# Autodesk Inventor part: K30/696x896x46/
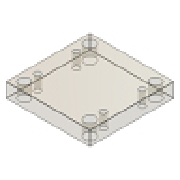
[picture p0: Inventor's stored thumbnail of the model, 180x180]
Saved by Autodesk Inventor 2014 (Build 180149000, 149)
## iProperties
IsCustomPart: 1
Created: 2009-11
Part Number: K30/696x896x46/
Material: DIN 1.1730
Description: Support Plate
Document SubType Name: Modeling
Designer: gaom
Standard Revision: 1
Manufacturer: HASCO
Language: en-US
Size Designation: 696x896x46/
Categories: <MemberInstance><Categories><Category DisplayName="Mold" InternalName="349578f2-f4d4-4954-8c09-8e99297a61c0" Mnemonic="MOLD"><Category DisplayName="Mold Plates"
Density: 7.82 g/cm^3
Appearance: Polycarbonate - Smoked
Author: gaom
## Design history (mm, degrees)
sketch "Sketch1"
  geometry: L1 (-348, 448)-(348, 448); L2 (348, 448)-(348, -448); L3 (348, -448)-(-348, -448); L4 (-348, -448)-(-348, 448); 5 further points
  constraints: 8 end point, 2 midpoint, 2 parallel, 1 horizontal, 1 horizontal alignment, 1 perpendicular, 1 vertical alignment
  dimensions: "d126" = 696 distance between parallel lines of L2 L4 (= W_); "d127" = 896 distance between parallel lines of L3 L1 (= L); "d130" = 296 horizontal distance of point (0, 0) point (-296, 337) (= 0.5 x S1_W); "d131" = 337 vertical distance of point (0, 0) point (-296, 337) (= 0.5 x S1_L); "d132" = 396 vertical distance of point (0, 0) point (-296, 396) (= 0.5 x LS_L); "d133" = 296 horizontal distance of point (0, 0) point (-296, 396) (= 0.5 x LS_W)
extrude "Extrusion1" new body sketch "Sketch1" distance "d20" = 46 (= H_); taper "d30" = 0 deg
sketch "Sketch2"
  geometry: 4 further points
hole "Hole12" sketch "Sketch2" at (-142, -279.032), (78, -279.032), (-78, 279.032), (142, 279.032) diameter "d176" = 3.4; stored, may be unused: countersink angle "d180" = 90 deg, drill point angle "d182" = 0 deg; dims "d177" = 6, "d178" = 4, "d179" = 2, "d181" = 8
sketch "Sketch3"
  geometry: 4 further points
hole "Hole13" sketch "Sketch3" at (-154, -180.032), (66, -180.032), (-66, 180.032), (154, 180.032) diameter "d183" = 3.4; stored, may be unused: countersink angle "d187" = 90 deg, drill point angle "d189" = 0 deg; dims "d184" = 6, "d185" = 4, "d186" = 2, "d188" = 8
sketch "Sketch4"
  geometry: 4 further points
hole "Hole14" sketch "Sketch4" at (-78, -279.032), (142, -279.032), (-142, 279.032), (78, 279.032) diameter "d190" = 3.4; stored, may be unused: countersink angle "d194" = 90 deg, drill point angle "d196" = 0 deg; dims "d191" = 6, "d192" = 4, "d193" = 2, "d195" = 8
sketch "Sketch5"
  geometry: 4 further points
hole "Hole15" sketch "Sketch5" at (-66, -180.032), (154, -180.032), (-154, 180.032), (66, 180.032) diameter "d197" = 3.4; stored, may be unused: countersink angle "d201" = 90 deg, drill point angle "d203" = 0 deg; dims "d198" = 6, "d199" = 4, "d200" = 2, "d202" = 8
sketch "Sketch6"
  geometry: 4 further points
hole "Hole16" sketch "Sketch6" at (-154, -65.032), (66, -65.032), (-66, 65.032), (154, 65.032) diameter "d204" = 3.4; stored, may be unused: countersink angle "d208" = 90 deg, drill point angle "d210" = 0 deg; dims "d205" = 6, "d206" = 4, "d207" = 2, "d209" = 8
sketch "Sketch7"
  geometry: 4 further points
hole "Hole17" sketch "Sketch7" at (-66, -65.032), (154, -65.032), (-154, 65.032), (66, 65.032) diameter "d211" = 3.4; stored, may be unused: countersink angle "d215" = 90 deg, drill point angle "d217" = 0 deg; dims "d212" = 6, "d213" = 4, "d214" = 2, "d216" = 8
workplane "Work Plane2"
workplane "Work Plane3"
workplane "Work Plane4"
workplane "Work Plane5"
feature "Sculpt13"
feature "Sculpt14"
feature "Sculpt15"
feature "Sculpt16"
body "Solid1"
hole "Hole1" sketch "Sketch1" diameter "d134" = 54 (= LS_dt); stored, may be unused: countersink angle "d138" = 90 deg, drill point angle "d140" = 0 deg; dims "d135" = 6, "d136" = 4, "d137" = 2, "d139" = 46 (= H_)
pattern_linear "Rectangular Pattern1" dims "d163" = 792 (computed from LS_L, Nl), "d166" = 592 (computed from LS_W, Nw)
hole "Hole2" sketch "Sketch1" diameter "d141" = 22 (= S1_dt); stored, may be unused: countersink angle "d145" = 90 deg, drill point angle "d147" = 0 deg; dims "d142" = 6, "d143" = 4, "d144" = 2, "d146" = 46 (= H_)
pattern_linear "Rectangular Pattern2" dims "d157" = 674 (computed from S1_L, Ns), "d160" = 592 (computed from S1_W, Nw)
chamfer "Chamfer1" distance "d173" = 0.5; stored, may be unused: second distance "d174" = 2, angle "d175" = 45 deg
feature "Surface13"
body "Srf13"
feature "Surface14"
body "Srf14"
feature "Surface15"
body "Srf15"
feature "Surface16"
body "Srf16"
other parameters: "L" = 896 [user parameter; used in 1 equation term], "W_" = 696 [user parameter; used in 1 equation term], "H_" = 46 [user parameter; used in 3 equation terms], "LS_W" = 592 [user parameter; used in 2 equation terms], "LS_dt" = 54 [user parameter; used in 1 equation term], "S1_L" = 674 [user parameter; used in 2 equation terms], "S1_W" = 592 [user parameter; used in 2 equation terms], "LS_L" = 792 [user parameter; used in 2 equation terms], "S1_dt" = 22 [user parameter; used in 1 equation term]
